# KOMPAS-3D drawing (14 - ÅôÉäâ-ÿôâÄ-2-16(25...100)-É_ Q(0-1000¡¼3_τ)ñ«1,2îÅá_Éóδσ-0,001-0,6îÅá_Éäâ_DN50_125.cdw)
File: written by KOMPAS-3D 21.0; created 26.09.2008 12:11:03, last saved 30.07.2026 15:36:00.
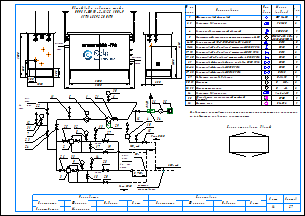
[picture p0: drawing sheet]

Sheets 1-2: A3, landscape

Document properties: Наименование: Макро:21; Автор: RaskoAdmin; Форматы листов документа: 2xA3; Полное имя файла: \\ur38nt01\Departments\КТО\КБ ПУРДГ\Заявки\Прайс-лист на типовые шкафы ГРПШ\ПУРДГ_стандарт_30_04_2026\ПУРДГ с РДГ(Н, В)\ПУРДГ-ШУГО-2-16(25...100)-Р_ Q(0-1000нм3_ч)до1,2МПа_Рвых-0,001-0,6МПа_РДГ_DN50_125.cdw

Title block, sheet 1: Наименование: Пункт учета газа / ПУГ-Ш-400-Р / ЛГТИ.485922.001ТУ; designation: ЛГТИ.03.4411141; sheet number: 1; Количество листов документа: 2; organisation: ООО "ЭЛЬСТЕР Газэлектроника"; Форматы листов документа: A3; stored path: C:\Рабочие документы\Компас\ПУГ\Схема.cdw; Разработал: Устинов; Проверил: Кошкин; Утвердил: Кошкин
Title block, sheet 2: sheet number: 2; stored path: D:\Рабочие документы\Заявки\ПУРДГ\ПУРДГ-ШУЭО-2-100-Р 4411220.cdw; designation, second copy: ЛГТИ.03.4411141-

Views: Вид 1, Вид 2
Referenced files: wcvoit.frw
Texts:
  Normal
  № на
  схеме
  Усл.
  обозн.
  Марка
  (модель)
  Кол.
  Фильтр газовый фланцевый
  ФГ 16-50
  Регулятор давления газа
  РДГ-50
  Клапан предохранительный сбросной
  КПС DN20
  Измерительный комплекс с ротационным счетчиком Ду50
  СГ-ЭК-Р-(0,2...2,0)-
  Кран кнопочный VE-РАСКО-НЗ-1,6-G1/2-М20
  DN15
  Кран шаровой "под приварку" штуцерный DN20 PN16
  DN20
  Кран шаровой "под приварку" штуцерный DN15 PN16
  Кран шаровой "под приварку" штуцерный п/п DN20 PN16
  Кран шаровой фланцевый с мех. приводом DN50 PN16
  Кран шаровой фланцевый DN50 PN16
  Кран шаровой фланцевый DN125 PN16
  DN50
  DN125
  Индикатор перепада давления
  Манометр
  Манометр-напоромер
  Обогреватель газогорелочный шкафной
  (Эльтон")
  Счетчик газа
  Delta 15
  0...     МПа
  0...     кПа
  Venio-A-15
  ОГШН
  BK-G1,6
  Общий вид и габариты шкафа
  ПУРДГ-ШУГО-2-16(25...100)-Р
  Выход газа
  Вход газа
  logo-rasko-ge.png
  DN 1
  местное
  сопротивление
  Римп DN20
  Выход
  газа
  Р=     кПа
  Вход
  Р=       МПа
  PDI
  Схема открывания дверей
  Предприятие изготовитель может заменять комплектующие на аналогичные,
  не ухудшающие заявленных характеристик.
  Должность
  Конструктор
  Фамилия
  Подпись
  Дата
  Согласовано
  Максимкин
  Лист
  Листов
  POLYLINE_STYLE_0.18_RGB_0_0_0
  POLYLINE_STYLE_0.50_RGB_0_0_0
  POLYLINE_STYLE_0.34_RGB_0_0_0
  PHANTOM_RGB_0_0_0_SC_1_THICK_0.18
  K5LT_THIN_RGB_0_0_0_THICK_0.18
  K5LT32769_RGB_0_0_0_THICK_0.18
  K5LT12_RGB_0_0_0_SC_1_THICK_0.18
  K5LT_DASHED_RGB_0_0_0_SC_1_THICK_0.18
  ACISOTGL_RGB_0_0_0_SC_0.8_THICK_0.25
  CONTINUOUS_RGB_0_127_31_THICK_0.3
  CONTINUOUS_RGB_0_0_255_THICK_0.35
  CONTINUOUS_RGB_255_0_0_THICK_0.35
  POLYLINE_STYLE_0.25_RGB_0_0_0
  CONTINUOUS_RGB_0_0_0_THICK_0.5
  POLYLINE_STYLE_0.35_RGB_0_0_255
  CONTINUOUS_RGB_0_0_0_THICK_0.4
  CONTINUOUS_RGB_0_0_0_THICK_0.35
  НЕВИДИМАЯ_RGB_0_0_0_SC_0.3_THICK_0.25
  СONTINUOUS_RGB_0_0_0_THICK_0.25
  ОСЕВАЯ2_RGB_248_153_30_SC_0.3_THICK_0.25
  Без оформления
Dimensions and other numbers on the sheet: 1; 2, 3; 2; 4; 5; 6-10; 11-16; 17, 18; 19, 20; 21; 22-26; 27, 28; 29; 30, 31; 32, 33; 34; 35; 36; 1500; 250; 300; 1050; 550; 305; 3000; 4130; 2000; 3300; 5,,,7DN 1; 7; 31; 12; 22; 23; 24; 11; 6; 30; 25; 32; 8; 13; 27; 19; 10; 15; 26; 33; 9; 3; 14; 28; 20; 17; 18; 16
